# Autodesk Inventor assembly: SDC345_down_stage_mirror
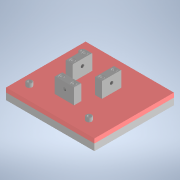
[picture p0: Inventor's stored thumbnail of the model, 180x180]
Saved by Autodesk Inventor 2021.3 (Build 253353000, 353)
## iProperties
Created: 2022-02
Part Number: SDC345_down_stage_mirror
Document SubType Name: Assembly
Designer: kengo
Author: kengo
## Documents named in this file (7)
- C:\Users\kengo\Documents\S2S_frame\SDC345\frame_misumi_ver12\stage\SDC345_down_stage_mirror.iam
- C:\Users\kengo\Documents\S2S_frame\SDC345\frame_misumi_ver12\stage\SDC3_Delstage.ipt
- C:\Users\kengo\Documents\S2S_frame\SDC345\frame_misumi_ver12\stage\SDC345_Alstage_mirror.ipt
- C:\Users\kengo\Documents\S2S_frame\SDC345\frame_misumi_ver12\stage\SCB8-15.ipt
- C:\Users\kengo\Documents\S2S_frame\SDC345\frame_misumi_ver12\stage\SCB8-35.ipt
- C:\Users\kengo\Documents\S2S_frame\SDC345\frame_misumi_ver12\stage\AJSN8-20.ipt
- C:\Users\kengo\Documents\S2S_frame\SDC345\frame_misumi_ver12\stage\SCB6-50.ipt
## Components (15 placed, 6 different names)
1. SDC3_Delstage:1 — メイト:1, フラッシュ:1, フラッシュ:2, 回転:2, 回転:3, 回転:4, 回転:5, 回転:6, 回転:7, 回転:12, 回転:15
2. SDC345_Alstage_mirror:1 — 回転:1, メイト:1, フラッシュ:1, フラッシュ:2
3. SCB8-15:1 — 回転:1
4. SCB8-35:1 — 回転:2
5. SCB8-35:2 — 回転:3
6. SCB8-35:3 — 回転:4
7. AJSN8-20:1 — 回転:5, 回転:13, 回転:14
8. AJSN8-20:2 — 回転:6, 回転:10, 回転:11
9. AJSN8-20:3 — 回転:7, 回転:8, 回転:9
10. SCB6-50:1 — 回転:8
11. SCB6-50:2 — 回転:9
12. SCB6-50:3 — 回転:10
13. SCB6-50:4 — 回転:11, 回転:12
14. SCB6-50:5 — 回転:13
15. SCB6-50:6 — 回転:14, 回転:15
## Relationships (18: RevoluteJoint 15, Flush 2, Mate 1)
- 回転:1 [RevoluteJoint]: SDC345_Alstage_mirror:1 ↔ SCB8-15:1
- メイト:1 [Mate]: SDC3_Delstage:1 ↔ SDC345_Alstage_mirror:1
- フラッシュ:1 [Flush]: SDC3_Delstage:1 ↔ SDC345_Alstage_mirror:1
- フラッシュ:2 [Flush]: SDC3_Delstage:1 ↔ SDC345_Alstage_mirror:1
- 回転:2 [RevoluteJoint]: SDC3_Delstage:1 ↔ SCB8-35:1
- 回転:3 [RevoluteJoint]: SDC3_Delstage:1 ↔ SCB8-35:2
- 回転:4 [RevoluteJoint]: SDC3_Delstage:1 ↔ SCB8-35:3
- 回転:5 [RevoluteJoint]: SDC3_Delstage:1 ↔ AJSN8-20:1
- 回転:6 [RevoluteJoint]: SDC3_Delstage:1 ↔ AJSN8-20:2
- 回転:7 [RevoluteJoint]: SDC3_Delstage:1 ↔ AJSN8-20:3
- 回転:8 [RevoluteJoint]: AJSN8-20:3 ↔ SCB6-50:1
- 回転:9 [RevoluteJoint]: AJSN8-20:3 ↔ SCB6-50:2
- 回転:10 [RevoluteJoint]: AJSN8-20:2 ↔ SCB6-50:3
- 回転:11 [RevoluteJoint]: AJSN8-20:2 ↔ SCB6-50:4
- 回転:12 [RevoluteJoint]: SDC3_Delstage:1 ↔ SCB6-50:4
- 回転:13 [RevoluteJoint]: AJSN8-20:1 ↔ SCB6-50:5
- 回転:14 [RevoluteJoint]: AJSN8-20:1 ↔ SCB6-50:6
- 回転:15 [RevoluteJoint]: SDC3_Delstage:1 ↔ SCB6-50:6
